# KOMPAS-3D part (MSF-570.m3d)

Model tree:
1. Ось X
2. Ось Y
3. Ось Z
4. Начало координат  (labels: Операция без истории:1)

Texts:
  Линия-выноска #1
  Линия-выноска #2
  Линия-выноска #3
  Отклонения формы и база
  Марка координационной оси
  Марка/позиционное обозначение с линией-выноской
  Марка/позиционное обозначение на линии
  Марка/позиционное обозначение без линии-выноски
